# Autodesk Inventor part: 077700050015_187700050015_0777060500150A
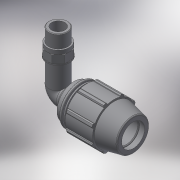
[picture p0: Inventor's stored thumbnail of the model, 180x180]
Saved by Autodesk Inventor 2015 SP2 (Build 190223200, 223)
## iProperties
Created: 2017-02
Part Number: 077700050015_187700050015_0777060500150A
Material: Generic
Description: PLASSON 90° ELBOW MALE WITH INTEGRAL BRASS THREAD 50-1.1/2"
Document SubType Name: Modeling
Designer: KIM
Mass: 174.249 g
Surface Area: 431.906 cm^2
Volume: 174.249 cm^3
Density: 1 g/cm^3
Appearance: Default
Author: KIM
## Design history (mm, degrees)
derived "07770.ipt"
feature "Solid1::07770.ipt"
tag "TaggingFeature1"
body "Solid1"
other parameters: "d4" = 12, "d5" = 36, "d7" = 96, "d9" = 20.57143, "d11" = 4.8, "d13" = 120 deg, "d15" = 12 deg, "d16" = 83.52, "d18" = 2.5, "d19" = 35 deg, "d20" = 17.5 deg, "d21" = 89.28, "d23" = 0, "d25" = 360 deg, "d27" = 1.92, "d33" = 1, "d42" = 53.28, "d43" = 2.88, "d46" = 1.5, "d51" = 144, "d68" = 9.6, "d72" = 97, "d73" = 47.803, "d74" = 22, "d75" = 54.97345, "d76" = 33.4621, "d79" = 19.1212, "d80" = 1.43409, "d83" = 0, "d84" = 0, "d91" = 72, "d93" = 93, "d94" = 47.803, "d95" = 33.4621, "d96" = 9.6, "d97" = 50 deg, "d98" = 2.4, "d99" = 81.0144, "d100" = 2.4, "d101" = 2.4, "d105" = 2.2, "d106" = 57.3636, "d107" = 22, "d108" = 13.2, "d109" = 0, "E_" = 96, "A_" = 144, "l_" = 93, "l_2" = 22, "A_1" = 97, "R_" = 47.803
